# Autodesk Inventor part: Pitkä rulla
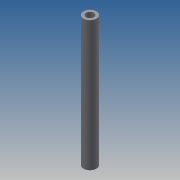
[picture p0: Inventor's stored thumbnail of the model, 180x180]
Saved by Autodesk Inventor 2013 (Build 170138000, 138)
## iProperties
Created: 2013-08
Part Number: Pitkä rulla
Material: Generic
Document SubType Name: Modeling
Designer: Reko Tuppurainen
Density: 1 g/cm^3
Author: Reko Tuppurainen
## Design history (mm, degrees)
sketch "Sketch1"
  geometry: C1 r 10 at (0, 0); 1 further point
  constraints: 1 centre point, 1 coincident
  dimensions: "d0" = 20 diameter of C1
extrude "Extrusion1" new body sketch "Sketch1" distance "d1" = 202; taper "d2" = 0 deg
sketch "Sketch2"
  geometry: C1 r 10 at (0, 0) reference; C2 r 6 at (0, 0)
  constraints: 1 centre point, 1 coincident
  dimensions: "d3" = 12 diameter of C2
extrude "Extrusion2" cut sketch "Sketch2" stored distance "d4" = 202; taper "d5" = 0 deg
body "Solid1"
